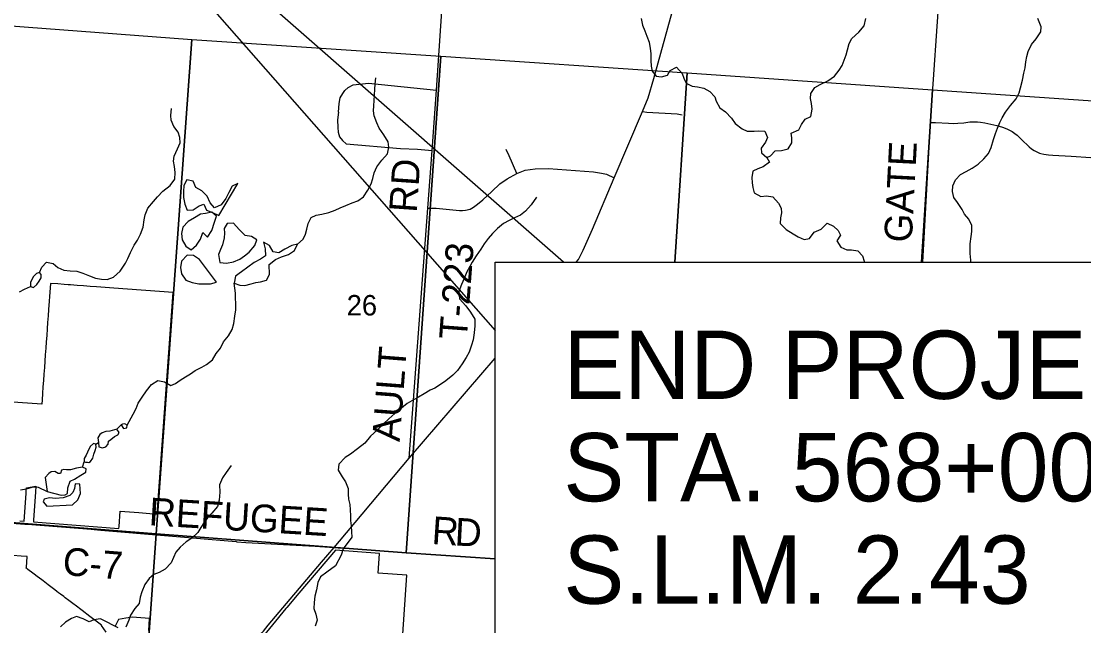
# Model space of a CAD drawing. Extents: x 0 to 34, y 0 to 26.1.
# Drawn here: x 27.339 to 29.516, y 15.797 to 17.037 of the extents above; entities that cross this region are included whole.
import ezdxf

# ---------------------------------------------------------------- set-up
doc = ezdxf.new("R2010")
doc.units = 0
for name, color, linetype in [('GM_X_County_Road', 7, 'Continuous'), ('GM_X_County_Road_Text', 7, 'Continuous'), ('GM_X_Minor_Lake', 7, 'Continuous'), ('GM_X_Minor_River', 7, 'Continuous'), ('GM_X_Section', 7, 'Continuous'), ('GM_X_Section_Text', 7, 'Continuous'), ('GM_X_Township_Road', 7, 'Continuous'), ('GM_X_Township_Road_Text', 7, 'Continuous'), ('SC_Scratch1', 7, 'Continuous'), ('SH_Data', 7, 'Continuous'), ('SH_Text', 7, 'Continuous')]:
    doc.layers.add(name, color=color, linetype=linetype)

msp = doc.modelspace()

# ---------------------------------------------------------------- linework, layer by layer
at = {"layer": 'GM_X_County_Road'}
for points in [[(28.4758, 16.5425), (28.4807, 16.5486), (28.4904, 16.5675), (28.5094, 16.6103), (28.5538, 16.7155), (28.6117, 16.8519), (28.6232, 16.8799), (28.6354, 16.9191), (28.7015, 17.1596), (28.7173, 17.2196), (28.7248, 17.2528), (28.727, 17.2681), (28.7321, 17.3175), (28.74, 17.4031), (28.7428, 17.4404)], [(27.9908, 15.9706), (28.1338, 16.141), (28.3097, 16.3459)], [(27.3012, 16.0092), (27.3465, 16.0057), (27.3516, 16.0054)], [(27.3516, 16.0054), (27.4819, 15.9953), (27.4882, 15.9948), (27.5017, 15.9937), (27.7796, 15.9699), (27.7805, 15.9698), (27.7994, 15.9682), (27.9412, 15.9608), (27.9801, 15.9578), (27.9881, 15.9573)], [(27.7631, 15.6967), (27.8322, 15.7828), (27.8353, 15.7866), (27.8446, 15.7983), (27.9541, 15.9281), (27.9801, 15.9578), (27.9908, 15.9706)], [(27.9881, 15.9573), (28.022, 15.9551), (28.3097, 15.9348)]]:
    msp.add_lwpolyline(points, dxfattribs=at)
at = {"layer": 'GM_X_Minor_Lake'}
for points in [[(27.7825, 16.704), (27.7714, 16.6984), (27.7641, 16.6856), (27.7583, 16.6735), (27.7483, 16.6603), (27.7349, 16.654), (27.726, 16.6644), (27.7201, 16.6781), (27.7092, 16.6888), (27.6968, 16.6962), (27.6912, 16.7088), (27.6784, 16.7116), (27.6718, 16.6999), (27.6713, 16.6877), (27.6712, 16.6752), (27.674, 16.6619), (27.6788, 16.6493), (27.6913, 16.6503), (27.7036, 16.6582), (27.7131, 16.6618), (27.7186, 16.6496), (27.7311, 16.6446), (27.7435, 16.6384)], [(27.7435, 16.6384), (27.7825, 16.704)], [(27.735, 16.6248), (27.7393, 16.6369), (27.7292, 16.645), (27.7166, 16.6425), (27.706, 16.641), (27.6938, 16.6336), (27.6809, 16.6265), (27.6701, 16.6145), (27.6673, 16.6016), (27.6687, 16.5883), (27.6761, 16.5753), (27.6874, 16.568), (27.6981, 16.5777), (27.7062, 16.5902), (27.7109, 16.6034), (27.7207, 16.5942), (27.7295, 16.6078)], [(27.7295, 16.6078), (27.735, 16.6248)], [(27.7459, 16.542), (27.7595, 16.5407), (27.7739, 16.5436), (27.7865, 16.5491), (27.7964, 16.5559), (27.8063, 16.5633), (27.8175, 16.5769), (27.8214, 16.5886), (27.8105, 16.5952), (27.798, 16.5976), (27.7856, 16.6099), (27.7736, 16.6229), (27.7611, 16.6219), (27.755, 16.6117), (27.7552, 16.6022), (27.7547, 16.5927), (27.7516, 16.5783), (27.7473, 16.5685), (27.7434, 16.5583)], [(27.787, 16.496), (27.7969, 16.4947), (27.8102, 16.4984), (27.8197, 16.501), (27.8292, 16.5028), (27.8417, 16.506), (27.8475, 16.5177), (27.8466, 16.5382), (27.8596, 16.5484), (27.8725, 16.5535), (27.8866, 16.5583), (27.8988, 16.5669), (27.905, 16.5798), (27.8932, 16.5772), (27.8787, 16.5698), (27.8665, 16.562), (27.8552, 16.5643), (27.8474, 16.5773), (27.8353, 16.5839), (27.839, 16.5702), (27.8396, 16.5558), (27.8293, 16.5491), (27.8163, 16.542), (27.803, 16.5323), (27.7904, 16.5233), (27.7778, 16.5139), (27.775, 16.4999)], [(27.7043, 16.5481), (27.6922, 16.5562), (27.6786, 16.5571), (27.6675, 16.545), (27.6651, 16.5322), (27.6672, 16.5189), (27.6762, 16.5062), (27.6894, 16.5008), (27.703, 16.4984), (27.7132, 16.4983), (27.7265, 16.4985), (27.739, 16.5018)], [(27.739, 16.5018), (27.7043, 16.5481)], [(27.7434, 16.5583), (27.7459, 16.542)], [(27.3763, 16.5215), (27.3702, 16.5193), (27.3641, 16.5137), (27.3579, 16.5016), (27.3582, 16.4932), (27.3642, 16.4909), (27.3707, 16.4973), (27.3754, 16.5041), (27.38, 16.5108), (27.3797, 16.5173)], [(27.3797, 16.5173), (27.3763, 16.5215)], [(27.775, 16.4999), (27.787, 16.496)], [(27.4972, 16.173), (27.4978, 16.1642), (27.5054, 16.1623), (27.5122, 16.1641), (27.5172, 16.1694), (27.518, 16.1758), (27.5222, 16.1792), (27.5303, 16.1852), (27.5371, 16.1885), (27.5394, 16.1938), (27.5346, 16.2003), (27.5205, 16.1966), (27.5122, 16.1956), (27.505, 16.1926), (27.5, 16.1893), (27.4961, 16.1825)], [(27.5486, 16.2017), (27.5551, 16.2031), (27.5559, 16.2084), (27.551, 16.2111), (27.5461, 16.2108), (27.5438, 16.2093)], [(27.5438, 16.2093), (27.5486, 16.2017)], [(27.4961, 16.1825), (27.4972, 16.173)], [(27.4744, 16.1326), (27.4774, 16.1322), (27.4812, 16.1344), (27.4855, 16.1408), (27.4878, 16.1495), (27.4902, 16.1567), (27.4925, 16.1635), (27.4915, 16.1696), (27.4869, 16.1712), (27.48, 16.1648), (27.475, 16.1531), (27.4723, 16.1474), (27.4677, 16.1403), (27.4676, 16.1334)], [(27.4676, 16.1334), (27.4704, 16.133), (27.4744, 16.1326)], [(27.3923, 16.0727), (27.421, 16.0652), (27.429, 16.0655), (27.4339, 16.0689), (27.4344, 16.0799), (27.4395, 16.0939), (27.4483, 16.098), (27.4612, 16.1062), (27.4711, 16.1121), (27.472, 16.119), (27.4644, 16.1225), (27.4523, 16.1207), (27.4401, 16.117), (27.4318, 16.1171), (27.4265, 16.1179), (27.4212, 16.1165), (27.4192, 16.1093), (27.4143, 16.1093), (27.4079, 16.1139), (27.4003, 16.1133), (27.3954, 16.1099), (27.3877, 16.1016)], [(27.3912, 16.0428), (27.4439, 16.0456), (27.455, 16.0558), (27.4604, 16.0686), (27.4591, 16.0876), (27.4497, 16.0885), (27.4484, 16.0786), (27.4449, 16.0707), (27.4388, 16.0643), (27.4247, 16.0595), (27.4092, 16.0585), (27.3971, 16.0594), (27.3861, 16.0569), (27.3841, 16.0512)], [(27.3877, 16.1016), (27.3923, 16.0727)], [(27.3841, 16.0512), (27.3912, 16.0428)]]:
    msp.add_lwpolyline(points, dxfattribs=at)
at = {"layer": 'GM_X_Minor_River'}
for points in [[(28.6093, 17.0424), (28.6118, 17.029), (28.6166, 17.0172), (28.621, 17.0065), (28.6254, 16.9936), (28.6279, 16.9807), (28.629, 16.9704), (28.6288, 16.9564), (28.6294, 16.9446), (28.6316, 16.9343), (28.6402, 16.924)], [(28.8668, 16.7573), (28.8741, 16.761), (28.884, 16.7711), (28.8965, 16.7721), (28.9106, 16.775), (28.9179, 16.7875), (28.9176, 16.7977), (28.9166, 16.8072), (28.9322, 16.8139), (28.9373, 16.8249), (28.9449, 16.8358), (28.9568, 16.8417), (28.9592, 16.8565), (28.9582, 16.8683), (28.9564, 16.8786), (28.9565, 16.8884), (28.965, 16.9009), (28.9756, 16.9068), (28.9913, 16.9143), (29.005, 16.924), (29.0146, 16.9364), (29.0208, 16.9462), (29.025, 16.9568), (29.029, 16.9682), (29.0321, 16.9784), (29.0353, 16.9909), (29.0411, 17.0014), (29.0552, 17.0142), (29.0663, 17.0274), (29.0695, 17.0421)], [(29.2849, 16.5425), (29.2843, 16.5472), (29.2833, 16.5605), (29.283, 16.5711), (29.2831, 16.5806), (29.2852, 16.5954), (29.2864, 16.606), (29.2866, 16.6182), (29.2806, 16.6311), (29.2717, 16.6415), (29.2665, 16.651), (29.2571, 16.6652), (29.2497, 16.6751), (29.2472, 16.688), (29.2477, 16.699), (29.2531, 16.7119), (29.2634, 16.7224), (29.2749, 16.7287), (29.2875, 16.7358), (29.2993, 16.7437), (29.3115, 16.7549), (29.3207, 16.7658), (29.3262, 16.7776), (29.3313, 16.7946), (29.3352, 16.8063), (29.3391, 16.8173), (29.3441, 16.829), (29.3488, 16.8388), (29.3557, 16.8505), (29.3657, 16.8637), (29.3776, 16.8776), (29.3834, 16.8901), (29.3866, 16.9003), (29.3902, 16.9162), (29.3934, 16.9306), (29.3957, 16.9412), (29.3974, 16.9537), (29.3994, 16.9647), (29.4018, 16.9749), (29.4088, 16.9889), (29.4184, 17.0005), (29.428, 17.0149), (29.4288, 17.0251), (29.4222, 17.0426)], [(28.6402, 16.924), (28.6508, 16.9227), (28.6629, 16.926), (28.6687, 16.9358), (28.6817, 16.9425), (28.6929, 16.9295), (28.6966, 16.92), (28.701, 16.9101), (28.7135, 16.9039), (28.7244, 16.9026), (28.7377, 16.8994), (28.7497, 16.8929), (28.7598, 16.8821), (28.7631, 16.8726), (28.7706, 16.8592), (28.7822, 16.8511), (28.7942, 16.8381), (28.802, 16.8274), (28.8163, 16.8163), (28.8265, 16.8116), (28.8405, 16.8114), (28.8504, 16.8121), (28.8625, 16.8116), (28.868, 16.7986), (28.8641, 16.7888), (28.8553, 16.7764), (28.8559, 16.7669), (28.8668, 16.7573), (28.8724, 16.7477), (28.8594, 16.7384), (28.848, 16.7339), (28.8381, 16.7295), (28.8357, 16.7162), (28.8363, 16.7052), (28.8377, 16.6957), (28.8407, 16.6847), (28.8546, 16.6773), (28.8656, 16.6787), (28.8792, 16.6771), (28.8908, 16.664), (28.896, 16.6537), (28.897, 16.6442), (28.8943, 16.634), (28.8942, 16.6219), (28.9065, 16.6096), (28.9204, 16.6007), (28.9306, 16.5949), (28.943, 16.5891), (28.9541, 16.5916), (28.9637, 16.6041), (28.9778, 16.6108), (28.9904, 16.6228), (29.0032, 16.6169), (29.0129, 16.6077), (29.0174, 16.5982), (29.0101, 16.5865), (29.0183, 16.5739), (29.0303, 16.5681), (29.0398, 16.5684), (29.053, 16.5659), (29.0624, 16.556), (29.0661, 16.5449), (29.067, 16.5425)], [(27.905, 16.5798), (27.9169, 16.5903), (27.9211, 16.6005), (27.9239, 16.6103), (27.927, 16.6224), (27.9332, 16.6341), (27.9431, 16.6393), (27.9549, 16.6415), (27.969, 16.6444), (27.9819, 16.6496), (27.9925, 16.6544), (28.0043, 16.6592), (28.0169, 16.6644), (28.0283, 16.6684), (28.0401, 16.6767), (28.0494, 16.6902), (28.0556, 16.7035), (28.0591, 16.7144), (28.0619, 16.7258), (28.0677, 16.7382), (28.0781, 16.7522), (28.0892, 16.7646), (28.092, 16.7786), (28.0906, 16.7892), (28.082, 16.8038), (28.0723, 16.8175), (28.0672, 16.8286), (28.0624, 16.8427), (28.061, 16.8533), (28.0611, 16.8632), (28.062, 16.8742), (28.0628, 16.8852), (28.0634, 16.8977), (28.0642, 16.9079), (28.0655, 16.9208)], [(27.3763, 16.5215), (27.3813, 16.5325), (27.3909, 16.5426), (27.4042, 16.5402), (27.4139, 16.5321), (27.426, 16.5263), (27.4392, 16.5254), (27.4529, 16.5241), (27.4649, 16.5206), (27.4789, 16.5147), (27.491, 16.5101), (27.5034, 16.5077), (27.5152, 16.5075), (27.5281, 16.5123), (27.5419, 16.5243), (27.5523, 16.5406), (27.5573, 16.5504), (27.5631, 16.5628), (27.5701, 16.5776), (27.577, 16.5881), (27.5836, 16.6002), (27.5887, 16.6149), (27.5911, 16.6293), (27.5927, 16.6396), (27.5986, 16.6532), (27.6097, 16.6671), (27.6181, 16.6769), (27.6293, 16.6885), (27.6438, 16.7001), (27.6534, 16.7133), (27.6543, 16.7266), (27.6529, 16.7388), (27.6511, 16.7502), (27.652, 16.7604), (27.6594, 16.7751), (27.6644, 16.7876), (27.6642, 16.7986), (27.6605, 16.8093), (27.6519, 16.8211), (27.646, 16.8341), (27.6453, 16.8436), (27.6466, 16.8576)], [(28.3947, 16.6764), (28.3835, 16.6606), (28.372, 16.6474), (28.3621, 16.6395), (28.3499, 16.6336), (28.3389, 16.6284), (28.3271, 16.6221), (28.3145, 16.6116), (28.3045, 16.6014), (28.2957, 16.5916), (28.2876, 16.5803), (28.2803, 16.5698), (28.2714, 16.5558), (28.263, 16.5426), (28.2572, 16.5328), (28.2518, 16.523), (28.2467, 16.509), (28.2409, 16.4973), (28.2358, 16.483), (28.2371, 16.4678), (28.2499, 16.4536), (28.2596, 16.4406), (28.2685, 16.4257), (28.2684, 16.412), (28.2671, 16.398), (28.265, 16.3836), (28.2615, 16.3726), (28.2564, 16.3586), (28.2506, 16.3477), (28.2421, 16.3341), (28.2329, 16.3209), (28.223, 16.3112), (28.2088, 16.2995), (28.1962, 16.291), (28.1867, 16.2846), (28.1768, 16.2801), (28.1642, 16.2731), (28.1528, 16.266), (28.1394, 16.2585), (28.1299, 16.2529), (28.1146, 16.2409), (28.1047, 16.2327), (28.0924, 16.2214), (28.081, 16.2117), (28.0687, 16.1993), (28.0549, 16.1862), (28.0427, 16.1719), (28.0278, 16.1599), (28.0136, 16.149), (28.0029, 16.1423), (27.9899, 16.1284), (27.9883, 16.1166), (27.9964, 16.1025), (28.0035, 16.0926), (28.0091, 16.0785), (28.0089, 16.0671), (28.0092, 16.0572), (28.0121, 16.0458), (28.0132, 16.0352), (28.0134, 16.023), (28.0137, 16.0131), (28.0147, 16.0021), (28.0157, 15.99), (28.016, 15.979), (27.9983, 15.9549), (27.9947, 15.942), (27.9831, 15.9201), (27.9648, 15.9074), (27.9518, 15.898), (27.9468, 15.8863), (27.9436, 15.8712), (27.9408, 15.8583), (27.9388, 15.8454), (27.9382, 15.8325), (27.9427, 15.8215), (27.9456, 15.8089), (27.9413, 15.7968)], [(27.3357, 16.4821), (27.3453, 16.4873), (27.3582, 16.4932)], [(27.5559, 16.2084), (27.5683, 16.2314), (27.5741, 16.2428), (27.5787, 16.2537), (27.5868, 16.2658), (27.5957, 16.279), (27.606, 16.2918), (27.619, 16.3), (27.6326, 16.2976), (27.6458, 16.2902), (27.6553, 16.2939), (27.6649, 16.3007), (27.6755, 16.3078), (27.6855, 16.3141), (27.695, 16.3208), (27.7087, 16.3279), (27.7182, 16.3331), (27.7305, 16.3425), (27.7382, 16.3553), (27.747, 16.3666), (27.7532, 16.3794), (27.7639, 16.3915), (27.7709, 16.4047), (27.7744, 16.4172), (27.7769, 16.4323), (27.7785, 16.4452), (27.7787, 16.4574), (27.778, 16.4695), (27.7778, 16.479), (27.775, 16.4999)], [(27.5346, 16.2003), (27.5438, 16.2093)], [(27.4915, 16.1696), (27.4972, 16.173)], [(27.4644, 16.1225), (27.4676, 16.1334)], [(27.769, 16.1257), (27.7587, 16.1118), (27.751, 16.1005), (27.7455, 16.0865), (27.7457, 16.071), (27.7448, 16.055), (27.7409, 16.0418), (27.7297, 16.0282), (27.7209, 16.0185), (27.7132, 16.0087), (27.7071, 15.9989), (27.7009, 15.9887), (27.6886, 15.9771), (27.6772, 15.9692), (27.6646, 15.9583), (27.6554, 15.9486), (27.6507, 15.9376), (27.6464, 15.9263), (27.6338, 15.9131), (27.6216, 15.9068), (27.6106, 15.9023), (27.601, 15.8945), (27.5925, 15.882), (27.5859, 15.8669), (27.5828, 15.8563), (27.5808, 15.8431), (27.5719, 15.8329), (27.5631, 15.8193), (27.5595, 15.8087), (27.553, 15.7948)], [(27.3374, 16.076), (27.3499, 16.0781), (27.364, 16.0821), (27.3735, 16.0813), (27.3923, 16.0727)], [(27.5374, 15.7934), (27.5269, 15.7985), (27.5152, 15.8047), (27.5012, 15.8113), (27.4876, 15.8099), (27.4781, 15.8054), (27.466, 15.8116), (27.4524, 15.8163), (27.4418, 15.8126), (27.4296, 15.8048), (27.4192, 15.7954)]]:
    msp.add_lwpolyline(points, dxfattribs=at)
at = {"layer": 'GM_X_Section'}
for points in [[(27.1906, 17.0366), (27.6883, 16.9993), (27.6154, 15.9857), (27.1167, 16.0245)], [(27.6883, 16.9993), (28.1989, 16.9652), (28.1277, 15.9466), (27.6154, 15.9857)], [(26.603, 16.0634), (26.6185, 16.0611), (27.1167, 16.0245), (27.6154, 15.9857), (27.5444, 14.9891), (26.5367, 15.0651)]]:
    msp.add_lwpolyline(points, close=True, dxfattribs=at)
for points in [[(28.3097, 15.9346), (28.1277, 15.9466), (28.1989, 16.9652), (28.7034, 16.9313), (28.6779, 16.5425)], [(28.6779, 16.5425), (28.7034, 16.9313), (29.2063, 16.8961), (29.1833, 16.5425)], [(29.1833, 16.5425), (29.2063, 16.8961), (29.7144, 16.8614), (29.6947, 16.5425)], [(28.6244, 15.7025), (28.5788, 14.9085), (27.5444, 14.9891), (27.6154, 15.9857), (28.1277, 15.9466), (28.3097, 15.9346)]]:
    msp.add_lwpolyline(points, dxfattribs=at)
at = {"layer": 'GM_X_Township_Road'}
for points in [[(28.1338, 16.141), (28.1718, 16.6538), (28.1808, 16.7721), (28.19, 16.8952), (28.2116, 17.2202), (28.2271, 17.3683), (28.2352, 17.4764)], [(29.186, 16.5425), (29.2021, 16.8295), (29.2414, 17.4013)], [(27.9891, 16.8504), (27.9907, 16.8683), (27.9926, 16.8796), (27.9976, 16.8887), (28.0018, 16.8948), (28.009, 16.9012), (28.0193, 16.9061), (28.0505, 16.9101), (28.19, 16.8952)], [(27.9891, 16.8504), (27.9867, 16.8345), (27.9875, 16.819), (27.9882, 16.8091), (27.9912, 16.8), (27.9969, 16.792), (28.0044, 16.7851), (28.1161, 16.7756), (28.151, 16.7743), (28.1808, 16.7721)], [(28.6117, 16.8519), (28.6204, 16.8501), (28.6827, 16.8468), (28.6934, 16.845)], [(29.2021, 16.8295), (29.2125, 16.8293), (29.2391, 16.8276), (29.2484, 16.8274), (29.2577, 16.8277), (29.2701, 16.8288), (29.2825, 16.8302), (29.2918, 16.8306), (29.2981, 16.8304), (29.3043, 16.8299), (29.3135, 16.8284), (29.3257, 16.8259), (29.3378, 16.8229), (29.3497, 16.8193), (29.3584, 16.816), (29.3641, 16.8134), (29.3695, 16.8104), (29.3747, 16.8069), (29.3794, 16.8029), (29.3886, 16.7944), (29.4041, 16.7791), (29.4089, 16.7751), (29.4141, 16.7717), (29.4196, 16.7688), (29.4253, 16.7664), (29.4283, 16.7654), (29.4343, 16.7642), (29.4436, 16.7629), (29.4529, 16.762), (29.4902, 16.7599), (29.5306, 16.7571)], [(28.3541, 16.7248), (28.3389, 16.761), (28.3327, 16.7735)], [(28.1718, 16.6538), (28.1888, 16.6533), (28.2367, 16.649), (28.2431, 16.649), (28.2495, 16.6495), (28.2589, 16.6518), (28.2653, 16.6557), (28.274, 16.6619), (28.2847, 16.6709), (28.303, 16.6875), (28.3195, 16.7034), (28.3344, 16.7134), (28.3541, 16.7248), (28.3713, 16.7317), (28.3917, 16.7344), (28.419, 16.7348), (28.5115, 16.7282), (28.5281, 16.7255), (28.5384, 16.7231), (28.5538, 16.7155)]]:
    msp.add_lwpolyline(points, dxfattribs=at)
at = {"layer": 'SC_Scratch1'}
for points in [[(27.3363, 16.0127), (27.3448, 16.0121), (27.3488, 16.0687), (27.3491, 16.0739), (27.3496, 16.08), (27.3689, 16.0835), (27.368, 16.0711), (27.364, 16.0145), (27.364, 16.0106), (27.5392, 15.9969), (27.5395, 16.0007), (27.5418, 16.0324), (27.5796, 16.0295), (27.6174, 16.0265), (27.6277, 16.1681), (27.6504, 16.4805), (27.529, 16.4895), (27.5196, 16.4902), (27.4931, 16.4922), (27.4799, 16.4932), (27.4667, 16.4942), (27.4535, 16.4951), (27.4402, 16.4961), (27.4349, 16.4965), (27.427, 16.4971), (27.4138, 16.4981), (27.3987, 16.4992), (27.3968, 16.4725), (27.3961, 16.4631), (27.3949, 16.4457), (27.3939, 16.4325), (27.393, 16.4192), (27.392, 16.406), (27.3911, 16.3928), (27.3901, 16.3796), (27.3892, 16.3663), (27.3882, 16.3531), (27.3873, 16.3399), (27.3863, 16.3267), (27.3854, 16.3135), (27.3844, 16.3002), (27.3835, 16.287), (27.3825, 16.2738), (27.3816, 16.2606), (27.3809, 16.2514), (27.292, 16.258)], [(27.5131, 15.784), (27.5037, 15.7981), (27.5031, 15.7986), (27.4898, 15.8087), (27.4874, 15.8105), (27.4793, 15.8167), (27.4638, 15.8284), (27.4492, 15.8395), (27.4477, 15.8407), (27.4472, 15.8411), (27.442, 15.845), (27.4366, 15.8491), (27.429, 15.8549), (27.4274, 15.8561), (27.4261, 15.8571), (27.4196, 15.862), (27.4155, 15.8651), (27.412, 15.8678), (27.4114, 15.8682), (27.4111, 15.8685), (27.4049, 15.8731), (27.3944, 15.8812), (27.3838, 15.8892), (27.3733, 15.8972), (27.3724, 15.8978), (27.3681, 15.9011), (27.3657, 15.9029), (27.3627, 15.9052), (27.3528, 15.9127), (27.3509, 15.9142), (27.3492, 15.9155), (27.3493, 15.9157), (27.3494, 15.9177), (27.3502, 15.9278), (27.3511, 15.9391), (27.3391, 15.94), (27.3217, 15.9414)], [(28.1154, 15.6996), (28.1288, 15.9009), (28.0706, 15.9049), (28.0733, 15.9455), (27.9828, 15.9523), (27.9079, 15.8642), (27.883, 15.835), (27.881, 15.8325), (27.8265, 15.7659)], [(27.6001, 15.7874), (27.6019, 15.8126), (27.5839, 15.8139), (27.566, 15.8152), (27.5583, 15.8138), (27.553, 15.8129), (27.5383, 15.8104), (27.5304, 15.7953)]]:
    msp.add_lwpolyline(points, dxfattribs=at)
at = {"layer": 'SH_Data'}
for points in [[(28.4497, 16.5425), (27.3097, 17.5425), (28.3097, 16.4025), (28.3097, 16.5425)], [(28.3097, 16.5425), (29.9598, 16.5425), (29.9598, 15.7025), (28.3097, 15.7025)]]:
    msp.add_lwpolyline(points, close=True, dxfattribs=at)

# ---------------------------------------------------------------- texts
at = {"layer": 'GM_X_County_Road_Text'}
for s, height, rotation, p in [('REFUGEE', 0.05682, 356.4898, (27.5995, 16.0036)), ('R', 0.0568, 356.2467, (28.1789, 15.9652)), ('D', 0.0568, 357.0592, (28.2263, 15.9621)), ('C-7', 0.05682, 355.4277, (27.4224, 15.9018))]:
    msp.add_text(s, height=height, rotation=rotation, dxfattribs=at).set_placement(p)
at = {"layer": 'GM_X_Section_Text'}
msp.add_text('26', height=0.04186, rotation=0, dxfattribs=at).set_placement((28.0058, 16.4336))
at = {"layer": 'GM_X_Township_Road_Text'}
for s, rotation, p in [('GATE', 87.0397, (29.1635, 16.5822)), ('RD', 86.0533, (28.1493, 16.6434)), ('T-223', 85.7741, (28.2517, 16.3829)), ('AULT', 85.6205, (28.1143, 16.1736))]:
    msp.add_text(s, height=0.05682, rotation=rotation, dxfattribs=at).set_placement(p)
at = {"layer": 'SH_Text'}
for s, p in [('END PROJECT', (28.4497, 16.2625)), ('STA. 568+00.00', (28.4497, 16.0525)), ('S.L.M. 2.43', (28.4497, 15.8425))]:
    msp.add_text(s, height=0.14, dxfattribs=at).set_placement(p)

doc.saveas('drawing.dxf')
